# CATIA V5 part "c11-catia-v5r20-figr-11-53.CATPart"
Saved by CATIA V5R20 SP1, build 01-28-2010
Part number: Part1
Bounding box of the stored display mesh (mm): x -55 to 55, y -105 to 155, z -20 to 14.953
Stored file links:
  D:\v5_r20\psrt_files_downloaded\c11\c11-catia-v5r20-figr-11-53.CATPart
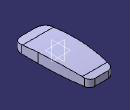
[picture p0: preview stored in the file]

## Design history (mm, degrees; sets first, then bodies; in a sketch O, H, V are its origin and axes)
Set1
  Extrude1: Element1 Sketch2, Lim1 50, Lim2 50, Direction yz-plane
  Sketch1 on xy-plane, origin (0, 0, 0), H (1, 0, 0), V (0, 1, 0)
    arc A1 centre (25, -75) radius 25 from (25, -100) to (50, -75) ccw
    line L1 (50, -75) -> (50, -15)
    point P4 (50, -15)
    arc A2 centre (-950, -15) radius 1000 from (50, -15) to (38.3367, 137.2843) ccw
    line L2 (23.5117, 150) -> (-23.5117, 150)
    line L3 (25, -100) -> (-25, -100)
    arc A3 centre (-25, -75) radius 25 from (-25, -100) to (-50, -75) cw
    line L4 (-50, -75) -> (-50, -15)
    point P9 (-50, -15)
    arc A4 centre (950, -15) radius 1000 from (-50, -15) to (-38.3367, 137.2843) cw
    reference projected line E1 (-50, -100) -> (50, -100) from edge of Extrude1
    axis line L5 (0, 170.4214) -> (0, -120.6595)
    point P11 (0, 170.4214)
    reference projected line E2 (50, -70) -> (50, 129.9971) from edge of Extrude1
    reference projected line E3 (-50, 129.9971) -> (-50, -70) from edge of Extrude1
    reference projected line E4 (-50, -100) -> (50, -100) from edge of Extrude1
    reference projected line E5 (50, 150) -> (-50, 150) from edge of Extrude1
    arc A5 centre (-23.5117, 135) radius 15 from (-38.3367, 137.2843) to (-23.5117, 150) cw
    arc A6 centre (23.5117, 135) radius 15 from (38.3367, 137.2843) to (23.5117, 150) ccw
    distance E4 P4 = 85
    radius A2 = 1000
    radius A5 = 15
    radius A6 = 15
    radius A1 = 25
    radius A3 = 25
    radius A4 = 1000
    tangency: L1 A1, A2 L1, L3 A1, A3 L3, A4 L4, L5 A3, A5 L2, A5 A4, A6 A2, A6 L2, A3 L4
    horizontal: L2 H
    coincidence: L3 E1, P11 V, L1 E2, L4 E3, L2 E5
    symmetry: P4 P9 L5
  Extrude2: Element1 Sketch1, Lim1 50, Lim2 20, Direction xy-plane
  Split1: ToCut Extrude2, Cutting Extrude1
  Split2: ToCut Extrude1, Cutting Split1
  Join1: Elements (Split2; Split1)
Body1 (main body)
  Sketch2 on yz-plane, origin (0, 0, 0), H (0, 1, 0), V (0, 0, 1)
    point P1 (-100, 0)
    line L1 (-100, 0) -> (-70, 3.8724)
    point P2 (-70, 3.8724)
    arc A1 centre (26.0141, -739.9564) radius 750 from (-70, 3.8724) to (129.9971, 2.8003) cw
    point P4 (129.9971, 2.8003)
    line L2 (129.9971, 2.8003) -> (150, 0)
    point P5 (150, 0)
    distance P1 P5 = 250
    distance P1 O = 100
    radius A1 = 750
    distance P2 P4 = 200
    distance P2 V = 70
    coincidence: P1 H, P5 H
    tangency: A1 L1, L2 A1
  ThickSurface1: Surface Join1, TopOffset 5, BotOffset 0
